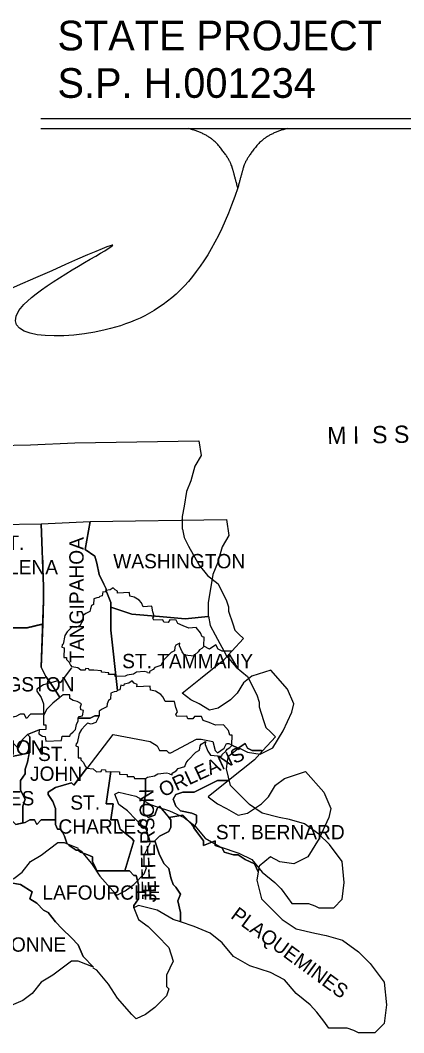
# Model space of a CAD drawing. Extents: x 0.19 to 2.82, y 0.04 to 1.79.
# Drawn here: x 2.4634 to 2.6012, y 1.3699 to 1.734 of the extents above; entities that cross this region are included whole.
import ezdxf

# ---------------------------------------------------------------- set-up
doc = ezdxf.new("R2010")
doc.units = 0
for name, color, linetype in [('Annotation', 7, 'Continuous'), ('Dist02', 7, 'Continuous'), ('Dist62', 7, 'Continuous'), ('Standard Info', 7, 'Continuous')]:
    doc.layers.add(name, color=color, linetype=linetype)

msp = doc.modelspace()

# ---------------------------------------------------------------- linework, layer by layer
at = {"layer": 'Annotation'}
for p, q in [((2.47085, 1.69871), (2.6123, 1.69871)), ((2.47085, 1.695), (2.6123, 1.695)), ((2.52387, 1.695), (2.55928, 1.695))]:
    msp.add_line(p, q, dxfattribs=at)
for points, degree in [([(2.54158, 1.67375), (2.54013, 1.67908), (2.53877, 1.68385), (2.53134, 1.69319), (2.52387, 1.695)], 2), ([(2.55928, 1.695), (2.55181, 1.69319), (2.54438, 1.68385), (2.54302, 1.67908), (2.54158, 1.67375)], 2), ([(2.54158, 1.67375), (2.53002, 1.63912), (2.4977, 1.61554), (2.42701, 1.62272), (2.54158, 1.67375), (2.42701, 1.62272)], 3)]:
    msp.add_open_spline(points, degree=degree, dxfattribs=at)
at = {"layer": 'Dist02'}
for points in [[(2.5294, 1.50908), (2.52924, 1.50867), (2.52865, 1.50808), (2.52782, 1.50758), (2.5274, 1.50692), (2.52615, 1.50575), (2.52607, 1.50533), (2.5224, 1.50567), (2.52157, 1.50683), (2.52065, 1.50908), (2.52074, 1.51), (2.51932, 1.50925), (2.51899, 1.50858), (2.51882, 1.50725), (2.51765, 1.50667), (2.51507, 1.504), (2.51449, 1.50308), (2.51399, 1.502), (2.51182, 1.50125), (2.51115, 1.5005), (2.5099, 1.49975), (2.50982, 1.49925), (2.50915, 1.49933), (2.50899, 1.49958), (2.50799, 1.49983), (2.50515, 1.49958), (2.50407, 1.49883), (2.50182, 1.4985), (2.50115, 1.49808)], [(2.53949, 1.50708), (2.53599, 1.50708), (2.53449, 1.50783), (2.53374, 1.50933), (2.5314, 1.50783), (2.5294, 1.50892)], [(2.52824, 1.49725), (2.53674, 1.50408)], [(2.53674, 1.50408), (2.53949, 1.50708)], [(2.4819, 1.50117), (2.47774, 1.49575), (2.47699, 1.4965), (2.47174, 1.495), (2.4694, 1.4935), (2.4694, 1.49275), (2.4709, 1.4905), (2.47174, 1.48817), (2.47174, 1.48442)], [(2.48982, 1.50033), (2.48824, 1.50025), (2.48807, 1.50075), (2.4869, 1.50092), (2.48674, 1.50033), (2.48515, 1.50025), (2.48407, 1.50117), (2.48199, 1.50142)], [(2.50115, 1.49808), (2.49757, 1.498), (2.4974, 1.49867), (2.49515, 1.49867), (2.49524, 1.49933), (2.49265, 1.4995), (2.49265, 1.50008), (2.48982, 1.50033)], [(2.5379, 1.4675), (2.53824, 1.46933), (2.54199, 1.47233), (2.54507, 1.47083), (2.54957, 1.47008), (2.55415, 1.47233), (2.5579, 1.47842), (2.56099, 1.48517), (2.56165, 1.48817), (2.5594, 1.4935), (2.5534, 1.50033), (2.54657, 1.49808), (2.54357, 1.49575), (2.54132, 1.492), (2.53899, 1.48967), (2.53449, 1.48667), (2.5314, 1.48592), (2.52765, 1.48817), (2.52465, 1.48967), (2.52165, 1.492), (2.52824, 1.49725)], [(2.47174, 1.48442), (2.46715, 1.48442), (2.46565, 1.48292), (2.4649, 1.48442), (2.4634, 1.48442), (2.46182, 1.48367), (2.45882, 1.48292), (2.45732, 1.48442), (2.45582, 1.48517), (2.45357, 1.48517), (2.44599, 1.48517), (2.44599, 1.48367), (2.44299, 1.48067), (2.44215, 1.47908), (2.44215, 1.47683), (2.44065, 1.47458), (2.4384, 1.47083), (2.4369, 1.4685)], [(2.51257, 1.45117), (2.51707, 1.44967), (2.52232, 1.44733), (2.52615, 1.44433), (2.5299, 1.43983), (2.53524, 1.43675), (2.54199, 1.4345), (2.54657, 1.43225), (2.55032, 1.42767), (2.5549, 1.42392), (2.55715, 1.42167), (2.5594, 1.41858), (2.56099, 1.41633), (2.56315, 1.41633), (2.56549, 1.41633), (2.56699, 1.41633), (2.56924, 1.41558), (2.57074, 1.41483), (2.57607, 1.41483), (2.57907, 1.41792), (2.57982, 1.42392), (2.57907, 1.4315), (2.57457, 1.43758), (2.57074, 1.44133), (2.56549, 1.44508), (2.56015, 1.44658), (2.5564, 1.44733), (2.55032, 1.44883), (2.54582, 1.45192), (2.53974, 1.45792), (2.53899, 1.45875), (2.53749, 1.46475), (2.5379, 1.46742)], [(2.4974, 1.45567), (2.4989, 1.45642), (2.50499, 1.45492), (2.51024, 1.45192), (2.51257, 1.45117)], [(2.48407, 1.43608), (2.48532, 1.43525), (2.48907, 1.43075), (2.49207, 1.42617), (2.49665, 1.42092), (2.49815, 1.41942), (2.50115, 1.42092), (2.50424, 1.42317), (2.50799, 1.427), (2.50874, 1.42917), (2.50799, 1.43), (2.50799, 1.43375), (2.51024, 1.43825), (2.50874, 1.44283), (2.50499, 1.44658), (2.50199, 1.44967), (2.4989, 1.45192), (2.4974, 1.45567)], [(2.41574, 1.43492), (2.41799, 1.43225), (2.42782, 1.4285), (2.43465, 1.42617), (2.44449, 1.42167), (2.44749, 1.42167), (2.45432, 1.42242), (2.45582, 1.42317), (2.46115, 1.42542), (2.46415, 1.42767), (2.46715, 1.4315), (2.4709, 1.43375), (2.47699, 1.43825), (2.47924, 1.43825), (2.48424, 1.43633)]]:
    msp.add_lwpolyline(points, dxfattribs=at)
at = {"layer": 'Dist62'}
for p, q in [((2.44915, 1.581), (2.46715, 1.58125)), ((2.46715, 1.58125), (2.48307, 1.582)), ((2.48307, 1.582), (2.52757, 1.58275))]:
    msp.add_line(p, q, dxfattribs=at)
for points in [[(2.52757, 1.58275), (2.5284, 1.57742), (2.52615, 1.57367), (2.52465, 1.56833), (2.52315, 1.56458), (2.52232, 1.55925), (2.52165, 1.5555), (2.52165, 1.551)], [(2.52174, 1.551), (2.52232, 1.548), (2.5239, 1.54492), (2.52765, 1.53808), (2.53074, 1.53433), (2.53449, 1.53133), (2.53749, 1.52525), (2.53824, 1.523), (2.53824, 1.5215), (2.53974, 1.51692), (2.54049, 1.51467), (2.54199, 1.51317), (2.54357, 1.51167), (2.53949, 1.50708)], [(2.5294, 1.50908), (2.52949, 1.51217), (2.52874, 1.51225), (2.52824, 1.51367), (2.52665, 1.51558), (2.52399, 1.51542), (2.5219, 1.51625), (2.51999, 1.517), (2.5194, 1.51825), (2.51715, 1.51833), (2.51657, 1.51742), (2.51499, 1.5175), (2.51465, 1.51833), (2.5114, 1.51825), (2.51107, 1.51892), (2.51157, 1.51975), (2.51107, 1.52125), (2.51065, 1.52325), (2.50757, 1.52308), (2.50699, 1.5245), (2.50615, 1.5255), (2.5044, 1.52658), (2.50282, 1.52683), (2.50265, 1.52817), (2.49832, 1.528), (2.4984, 1.52867), (2.49749, 1.52917), (2.49682, 1.52983), (2.49574, 1.52917), (2.49415, 1.52892), (2.49399, 1.52833), (2.49307, 1.52842), (2.49282, 1.527), (2.49207, 1.52675)], [(2.49207, 1.52675), (2.49165, 1.52642), (2.4909, 1.52625), (2.48982, 1.52592), (2.48974, 1.52392), (2.48907, 1.52358), (2.48865, 1.52233), (2.48849, 1.52142), (2.48699, 1.52067), (2.48607, 1.51992), (2.48607, 1.51842)], [(2.48607, 1.51842), (2.48549, 1.51742), (2.48499, 1.51633), (2.4834, 1.51567), (2.48224, 1.516), (2.48149, 1.51525), (2.48024, 1.51408), (2.47949, 1.51275), (2.4789, 1.50958), (2.47849, 1.50942), (2.4784, 1.50858), (2.47924, 1.50833), (2.47915, 1.50483), (2.48007, 1.50483), (2.48007, 1.50417), (2.4809, 1.50325), (2.48149, 1.50208), (2.48199, 1.50142)], [(2.53949, 1.50708), (2.53599, 1.50708), (2.53449, 1.50783), (2.53374, 1.50933), (2.5314, 1.50783), (2.5294, 1.50892)], [(2.4819, 1.50117), (2.47774, 1.49575), (2.47699, 1.4965), (2.47174, 1.495), (2.4694, 1.4935), (2.4694, 1.49275), (2.4709, 1.4905), (2.47174, 1.48817), (2.47174, 1.48442)], [(2.47174, 1.48442), (2.46715, 1.48442), (2.46565, 1.48292), (2.4649, 1.48442), (2.4634, 1.48442), (2.46182, 1.48367), (2.46115, 1.4835)]]:
    msp.add_lwpolyline(points, dxfattribs=at)
at = {"layer": 'Standard Info'}
for p, q in [((2.45121, 1.55259), (2.47101, 1.55286)), ((2.47101, 1.55286), (2.48852, 1.55369)), ((2.48852, 1.55369), (2.53747, 1.55451)), ((2.53096, 1.51959), (2.53105, 1.51968)), ((2.47156, 1.51684), (2.4712, 1.51684)), ((2.47019, 1.4788), (2.46606, 1.47715)), ((2.46606, 1.47715), (2.47019, 1.4788)), ((2.46606, 1.47715), (2.47019, 1.4788)), ((2.46441, 1.44552), (2.46441, 1.44534)), ((2.51685, 1.44726), (2.51675, 1.44726)), ((2.52583, 1.4436), (2.52592, 1.44387))]:
    msp.add_line(p, q, dxfattribs=at)
for points in [[(2.47101, 1.55286), (2.47184, 1.53041), (2.47184, 1.52546), (2.47156, 1.51684)], [(2.4777, 1.49044), (2.4777, 1.49044), (2.47605, 1.49301), (2.4744, 1.49548), (2.47266, 1.49796), (2.47101, 1.50135), (2.47184, 1.52546), (2.47184, 1.53041), (2.47101, 1.55286)], [(2.48852, 1.55369), (2.48678, 1.5437), (2.49017, 1.54122), (2.491, 1.53875), (2.49182, 1.53462), (2.49347, 1.53123), (2.4943, 1.52958), (2.4943, 1.52876), (2.49595, 1.52463), (2.49595, 1.51464), (2.49842, 1.49301)], [(2.49595, 1.52298), (2.49595, 1.52463), (2.4943, 1.52876), (2.4943, 1.52958), (2.49347, 1.53123), (2.49182, 1.53462), (2.491, 1.53875), (2.49017, 1.54122), (2.48678, 1.5437), (2.48852, 1.55369)], [(2.53747, 1.55451), (2.53839, 1.54874), (2.53591, 1.54461), (2.53426, 1.53875), (2.53261, 1.53462), (2.5317, 1.52876), (2.53096, 1.52463), (2.53096, 1.51959)], [(2.53096, 1.51959), (2.52262, 1.51876), (2.51345, 1.51959), (2.50346, 1.52041), (2.49595, 1.52298)], [(2.49842, 1.49301), (2.49595, 1.51464), (2.49595, 1.52298)], [(2.49595, 1.52298), (2.50346, 1.52041), (2.51345, 1.51959), (2.52262, 1.51876), (2.53096, 1.51959)], [(2.53105, 1.51968), (2.5317, 1.51629), (2.53344, 1.51299), (2.53756, 1.50547), (2.54095, 1.50135), (2.54508, 1.49796), (2.54838, 1.49136), (2.5492, 1.48879), (2.5492, 1.48714), (2.55085, 1.48219), (2.55168, 1.47971), (2.55333, 1.47806), (2.55507, 1.47632), (2.55058, 1.47137)], [(2.46606, 1.47715), (2.46441, 1.4755), (2.46267, 1.4722), (2.46185, 1.47302), (2.4602, 1.47467), (2.45855, 1.47715), (2.45442, 1.48136), (2.45103, 1.48384), (2.4469, 1.48714), (2.44443, 1.48971), (2.44113, 1.49218), (2.43939, 1.49548), (2.43856, 1.49878), (2.43856, 1.50208), (2.43856, 1.5063), (2.43939, 1.50877), (2.44113, 1.51207), (2.44351, 1.51464), (2.44415, 1.51556)], [(2.4712, 1.51684), (2.4657, 1.51546), (2.44397, 1.51546)], [(2.44434, 1.51546), (2.46606, 1.51546), (2.47156, 1.51684)], [(2.44434, 1.51546), (2.46606, 1.51546), (2.47156, 1.51684)], [(2.47156, 1.51684), (2.47101, 1.50135), (2.47266, 1.49796), (2.4744, 1.49548), (2.47605, 1.49301), (2.4777, 1.49044)], [(2.53949, 1.47348), (2.53958, 1.47687), (2.53875, 1.47696), (2.5382, 1.47861), (2.53646, 1.48063), (2.53353, 1.48045), (2.53124, 1.48146), (2.52913, 1.48219), (2.52849, 1.48356), (2.52601, 1.48366), (2.52537, 1.48274), (2.52363, 1.48274), (2.52326, 1.48375), (2.51969, 1.48356), (2.51932, 1.4843), (2.51987, 1.48531), (2.51932, 1.48686), (2.51886, 1.48906), (2.51547, 1.48897), (2.51483, 1.49053), (2.51391, 1.49154), (2.51199, 1.49273), (2.51025, 1.4931), (2.51006, 1.49456), (2.5053, 1.49429), (2.50539, 1.49511), (2.50438, 1.49566), (2.50365, 1.4964), (2.50245, 1.49566), (2.50071, 1.4953), (2.50053, 1.49466), (2.49952, 1.49484), (2.49925, 1.49319), (2.49842, 1.49301)], [(2.49842, 1.49301), (2.49796, 1.49255), (2.49714, 1.49246), (2.49595, 1.492), (2.49585, 1.48989), (2.49512, 1.48943), (2.49466, 1.48815), (2.49448, 1.48705), (2.49283, 1.48631), (2.49182, 1.48549), (2.49182, 1.48384)], [(2.4777, 1.49044), (2.47514, 1.48842), (2.47303, 1.48622), (2.47175, 1.48402), (2.47184, 1.48063), (2.47266, 1.48063), (2.47266, 1.47889), (2.47019, 1.4788), (2.46606, 1.47715)], [(2.4843, 1.48301), (2.48458, 1.48356), (2.48577, 1.48384), (2.48614, 1.48576), (2.48522, 1.48604), (2.48504, 1.48714), (2.4854, 1.48815), (2.48394, 1.48906), (2.48247, 1.48934), (2.48128, 1.49007), (2.48128, 1.49136), (2.4789, 1.49136), (2.4777, 1.49044)], [(2.44681, 1.48714), (2.45103, 1.48384), (2.45442, 1.48136), (2.45855, 1.47715), (2.4602, 1.47467), (2.46185, 1.47302), (2.46267, 1.4722), (2.46441, 1.4755), (2.46606, 1.47715), (2.46689, 1.47632), (2.46689, 1.47055)], [(2.47019, 1.4788), (2.4701, 1.47733), (2.47147, 1.4766), (2.47239, 1.47641), (2.47266, 1.47476), (2.47825, 1.47495), (2.47853, 1.47651), (2.48128, 1.47651), (2.48146, 1.47724), (2.48247, 1.47806), (2.4833, 1.47898), (2.48366, 1.48072), (2.4843, 1.4821), (2.4843, 1.48301)], [(2.49182, 1.48384), (2.49118, 1.48265), (2.49063, 1.48146), (2.48889, 1.48081), (2.4876, 1.48118), (2.48678, 1.48036), (2.4854, 1.47898), (2.48458, 1.47751), (2.48394, 1.47403), (2.48348, 1.47394), (2.48339, 1.47302), (2.4843, 1.47275), (2.48421, 1.46881), (2.48522, 1.46881), (2.48522, 1.46807), (2.48614, 1.46706), (2.48678, 1.46578), (2.48733, 1.46505)], [(2.49182, 1.48384), (2.49017, 1.48384), (2.48852, 1.48301), (2.4843, 1.48301)], [(2.4843, 1.48301), (2.48852, 1.48301), (2.49017, 1.48384), (2.49182, 1.48384)], [(2.46441, 1.44552), (2.46441, 1.44891), (2.46441, 1.45139), (2.46515, 1.45386), (2.4635, 1.45716), (2.4635, 1.45891), (2.4635, 1.46056), (2.46515, 1.46303), (2.46515, 1.46468), (2.46606, 1.46716), (2.46689, 1.47137), (2.46689, 1.47632), (2.46606, 1.47715)], [(2.48742, 1.46496), (2.49677, 1.47715), (2.51006, 1.47467), (2.51263, 1.47302), (2.51345, 1.47137), (2.51593, 1.47137), (2.51675, 1.47055), (2.51758, 1.47055), (2.52675, 1.4755), (2.5284, 1.4755), (2.53261, 1.47467), (2.53344, 1.47137), (2.53426, 1.47055), (2.53674, 1.4722), (2.53756, 1.47385), (2.53839, 1.47385), (2.5394, 1.47339)], [(2.48742, 1.46496), (2.49677, 1.47715), (2.51006, 1.47467), (2.51263, 1.47302), (2.51345, 1.47137), (2.51593, 1.47137), (2.51675, 1.47055), (2.51758, 1.47055), (2.52675, 1.4755), (2.5284, 1.4755), (2.53261, 1.47467), (2.53344, 1.47137), (2.53426, 1.47055), (2.53674, 1.4722), (2.53756, 1.47385), (2.53839, 1.47385), (2.5394, 1.47339)], [(2.50841, 1.46138), (2.50915, 1.46184), (2.51162, 1.4623), (2.51281, 1.46303), (2.51593, 1.4634), (2.51703, 1.46312), (2.51721, 1.46285), (2.51795, 1.46266), (2.51804, 1.46321), (2.51941, 1.46413), (2.52015, 1.46496), (2.52253, 1.46569), (2.52308, 1.46697), (2.52372, 1.46789), (2.52656, 1.47082), (2.52785, 1.47146), (2.52803, 1.47302), (2.5284, 1.47366), (2.52995, 1.47458), (2.52986, 1.47357), (2.53087, 1.4711), (2.53179, 1.46972), (2.53582, 1.46936), (2.53591, 1.46991), (2.53729, 1.4711), (2.53775, 1.47192), (2.53866, 1.47247), (2.5393, 1.47311), (2.53949, 1.47348)], [(2.53949, 1.4733), (2.54169, 1.4722), (2.54425, 1.47385), (2.54508, 1.4722), (2.54673, 1.47137), (2.55058, 1.47137)], [(2.55003, 1.47137), (2.54673, 1.47137), (2.54508, 1.4722), (2.54425, 1.47385), (2.54169, 1.4722), (2.53949, 1.4733)], [(2.55058, 1.47137), (2.54755, 1.46807)], [(2.46689, 1.47055), (2.4469, 1.46642), (2.44351, 1.46642), (2.44351, 1.46386), (2.44278, 1.46386), (2.44021, 1.46138), (2.43691, 1.46056), (2.43526, 1.46138), (2.43444, 1.46138), (2.43279, 1.46138), (2.43114, 1.46138), (2.43022, 1.46221), (2.42857, 1.46056)], [(2.44021, 1.46147), (2.44278, 1.46386), (2.44351, 1.46386), (2.44351, 1.46642), (2.4469, 1.46642), (2.46689, 1.47055)], [(2.4667, 1.47055), (2.46606, 1.46716), (2.46515, 1.46468), (2.46515, 1.46303), (2.4635, 1.46056), (2.4635, 1.45891), (2.4635, 1.45716), (2.46515, 1.45386), (2.46441, 1.45139), (2.46441, 1.44891), (2.46441, 1.44552)], [(2.54755, 1.46807), (2.5382, 1.46056)], [(2.48724, 1.46486), (2.48265, 1.45891), (2.48183, 1.45973), (2.47605, 1.45808), (2.47349, 1.45643), (2.47349, 1.45551), (2.47514, 1.45304), (2.47605, 1.45056), (2.47605, 1.44644)], [(2.47605, 1.44644), (2.47605, 1.45056), (2.47514, 1.45304), (2.47349, 1.45551), (2.47349, 1.45643), (2.47605, 1.45808), (2.48183, 1.45973), (2.48265, 1.45891), (2.48724, 1.46486)], [(2.48733, 1.46505), (2.48962, 1.46477), (2.49081, 1.46376), (2.49255, 1.46386), (2.49274, 1.4645), (2.49402, 1.46441), (2.4942, 1.46376), (2.49595, 1.46386)], [(2.49595, 1.46386), (2.4943, 1.45221), (2.49677, 1.45221), (2.49595, 1.44644), (2.49842, 1.44644), (2.49934, 1.44305), (2.50346, 1.43975), (2.50429, 1.43892), (2.50099, 1.42811)], [(2.50099, 1.42811), (2.50429, 1.43892), (2.50346, 1.43975), (2.49934, 1.44305), (2.49842, 1.44644), (2.49595, 1.44644), (2.49677, 1.45221), (2.4943, 1.45221), (2.49595, 1.46386)], [(2.49595, 1.46386), (2.49906, 1.46367), (2.49906, 1.46294), (2.5019, 1.46276), (2.50181, 1.46202), (2.50429, 1.46202), (2.50447, 1.46138), (2.50841, 1.46138)], [(2.5382, 1.46056), (2.53096, 1.45469), (2.53426, 1.45221), (2.53756, 1.45056), (2.54169, 1.44809), (2.54508, 1.44891), (2.55003, 1.45221), (2.5526, 1.45469), (2.55507, 1.45891), (2.55837, 1.46138), (2.56589, 1.46386), (2.57249, 1.45643), (2.57496, 1.45056), (2.57423, 1.44726), (2.57084, 1.43975), (2.56671, 1.43315), (2.56167, 1.43058), (2.55672, 1.43141), (2.55333, 1.43315), (2.5492, 1.42976), (2.54884, 1.42774)], [(2.50841, 1.46138), (2.50841, 1.45551), (2.50768, 1.45139), (2.50768, 1.44891), (2.50933, 1.44726), (2.5118, 1.44809), (2.51263, 1.45056), (2.51345, 1.45139), (2.51758, 1.44644), (2.51758, 1.44387), (2.51675, 1.44222), (2.5151, 1.4414), (2.51345, 1.44057), (2.5118, 1.43892), (2.51263, 1.43645), (2.51345, 1.43388), (2.5151, 1.43058), (2.51675, 1.42893), (2.51758, 1.42563), (2.5184, 1.42316), (2.51932, 1.42224), (2.52097, 1.41976), (2.52005, 1.41729), (2.52097, 1.41316), (2.52097, 1.40977)], [(2.51694, 1.44726), (2.51345, 1.45139), (2.51263, 1.45056), (2.5118, 1.44809), (2.50933, 1.44726), (2.50768, 1.44891), (2.50768, 1.45139), (2.50841, 1.45551), (2.50841, 1.46138)], [(2.5382, 1.46056), (2.53591, 1.46056), (2.53426, 1.46056), (2.53261, 1.45973), (2.52922, 1.45808), (2.52592, 1.45643), (2.5218, 1.45643), (2.51932, 1.45551), (2.5184, 1.45386), (2.51932, 1.45139), (2.52097, 1.44974), (2.5251, 1.44891), (2.52675, 1.44809), (2.52675, 1.44552), (2.52592, 1.44387)], [(2.52592, 1.44387), (2.52675, 1.44552), (2.52675, 1.44809), (2.5251, 1.44891), (2.52097, 1.44974), (2.51932, 1.45139), (2.5184, 1.45386), (2.51932, 1.45551), (2.5218, 1.45643), (2.52592, 1.45643), (2.52922, 1.45808), (2.53261, 1.45973), (2.53426, 1.46056), (2.53591, 1.46056), (2.5382, 1.46056)], [(2.43774, 1.42893), (2.43939, 1.43141), (2.44186, 1.43553), (2.44351, 1.4381), (2.44351, 1.44057), (2.44443, 1.44222), (2.44773, 1.44552), (2.44773, 1.44726), (2.45607, 1.44726), (2.45855, 1.44726), (2.4602, 1.44644), (2.46185, 1.44479), (2.46515, 1.44552), (2.46689, 1.44644), (2.46854, 1.44644), (2.46936, 1.44479), (2.47101, 1.44644), (2.47605, 1.44644)], [(2.46441, 1.44534), (2.46185, 1.44479), (2.4602, 1.44644), (2.45855, 1.44726), (2.45607, 1.44726), (2.44773, 1.44726), (2.44773, 1.44552), (2.4469, 1.4447)], [(2.47605, 1.44644), (2.47101, 1.44644), (2.46936, 1.44479), (2.46854, 1.44644), (2.46689, 1.44644), (2.46515, 1.44552), (2.46441, 1.44534)], [(2.47605, 1.44644), (2.47605, 1.44479), (2.47679, 1.44305), (2.4777, 1.44305), (2.47853, 1.44222), (2.47935, 1.44057), (2.48018, 1.4381), (2.481, 1.43727), (2.48348, 1.43553), (2.4843, 1.43553), (2.48513, 1.4348), (2.4877, 1.43388), (2.48935, 1.43315), (2.48935, 1.43141), (2.49017, 1.42976), (2.491, 1.42811), (2.50264, 1.42811), (2.50429, 1.42646), (2.50511, 1.42646), (2.50594, 1.42316), (2.50594, 1.42059), (2.50594, 1.41811), (2.50429, 1.41564), (2.50429, 1.41481)], [(2.50099, 1.42811), (2.491, 1.42811), (2.49017, 1.42976), (2.48935, 1.43141), (2.48935, 1.43315), (2.4877, 1.43388), (2.48513, 1.4348), (2.4843, 1.43553), (2.48348, 1.43553), (2.481, 1.43727), (2.48018, 1.4381), (2.47935, 1.44057), (2.47853, 1.44222), (2.4777, 1.44305), (2.47679, 1.44305), (2.47605, 1.44479), (2.47605, 1.44644)], [(2.52097, 1.40977), (2.52097, 1.41316), (2.52005, 1.41729), (2.52097, 1.41976), (2.51932, 1.42224), (2.5184, 1.42316), (2.51758, 1.42563), (2.51675, 1.42893), (2.5151, 1.43058), (2.51345, 1.43388), (2.51263, 1.43645), (2.5118, 1.43892), (2.51345, 1.44057), (2.5151, 1.4414), (2.51675, 1.44222), (2.51758, 1.44387), (2.51758, 1.44644), (2.51685, 1.44726)], [(2.52574, 1.44378), (2.5251, 1.44479), (2.5218, 1.44809), (2.51675, 1.44726)], [(2.51675, 1.44726), (2.5218, 1.44809), (2.5251, 1.44479), (2.52574, 1.44378)], [(2.54884, 1.42774), (2.54755, 1.43058), (2.54425, 1.43223), (2.54169, 1.43388), (2.54004, 1.43388), (2.53674, 1.4348), (2.53591, 1.43645), (2.53344, 1.43727), (2.53344, 1.43892), (2.52922, 1.43727), (2.52922, 1.43892), (2.52675, 1.44222), (2.52583, 1.4436)], [(2.52583, 1.4436), (2.52675, 1.44222), (2.52922, 1.43892), (2.52922, 1.43727), (2.53344, 1.43892), (2.53344, 1.43727), (2.53591, 1.43645), (2.53674, 1.4348), (2.54004, 1.43388), (2.54169, 1.43388), (2.54425, 1.43223), (2.54755, 1.43058), (2.54884, 1.42774)], [(2.43774, 1.42893), (2.44773, 1.42893), (2.44773, 1.43141), (2.45103, 1.43223), (2.45277, 1.43388), (2.45525, 1.43223), (2.45607, 1.43058), (2.45772, 1.42728), (2.45937, 1.42389), (2.4635, 1.42316), (2.46771, 1.42059), (2.46689, 1.41811), (2.46936, 1.41646), (2.47184, 1.41399), (2.47349, 1.41316), (2.47605, 1.40977), (2.47853, 1.4073), (2.48183, 1.404), (2.4843, 1.40152), (2.48605, 1.39731), (2.4898, 1.39346)], [(2.4898, 1.39346), (2.48605, 1.39731), (2.4843, 1.40152), (2.48183, 1.404), (2.47853, 1.4073), (2.47605, 1.40977), (2.47349, 1.41316), (2.47184, 1.41399), (2.46936, 1.41646), (2.46689, 1.41811), (2.46771, 1.42059), (2.4635, 1.42316), (2.45937, 1.42389), (2.45772, 1.42728), (2.45607, 1.43058), (2.45525, 1.43223), (2.45277, 1.43388), (2.45103, 1.43223), (2.44773, 1.43141), (2.44773, 1.42893), (2.43774, 1.42893)], [(2.50429, 1.41481), (2.50429, 1.41564), (2.50594, 1.41811), (2.50594, 1.42059), (2.50594, 1.42316), (2.50511, 1.42646), (2.50429, 1.42646), (2.50264, 1.42811), (2.50099, 1.42811)], [(2.54884, 1.42774), (2.54838, 1.42481), (2.55003, 1.41811), (2.55085, 1.41729), (2.55755, 1.4106), (2.5625, 1.4073), (2.56919, 1.40565), (2.57331, 1.40482), (2.57918, 1.40317), (2.58495, 1.39896), (2.58917, 1.39483), (2.59412, 1.38814), (2.59495, 1.37989), (2.59412, 1.3732), (2.59082, 1.3699), (2.58495, 1.3699), (2.5833, 1.37072), (2.58083, 1.37155), (2.57918, 1.37155), (2.57661, 1.37155), (2.57423, 1.37155), (2.57249, 1.37402), (2.57001, 1.37732), (2.56754, 1.37989), (2.5625, 1.38401), (2.55837, 1.38896), (2.55333, 1.39153), (2.5459, 1.39401), (2.54004, 1.39731), (2.53591, 1.40226), (2.5317, 1.40565), (2.52592, 1.40812), (2.52097, 1.40977)], [(2.50429, 1.41481), (2.50594, 1.4106), (2.50933, 1.40812), (2.51263, 1.40482), (2.51675, 1.40061), (2.5184, 1.39566), (2.51593, 1.39061), (2.51593, 1.38649), (2.51675, 1.38566), (2.51593, 1.38319), (2.5118, 1.37897), (2.50841, 1.3765), (2.50511, 1.37485), (2.50346, 1.3765), (2.49842, 1.38236), (2.49512, 1.38731), (2.491, 1.39236), (2.48962, 1.39318)], [(2.52097, 1.40977), (2.5184, 1.4106), (2.51263, 1.41399), (2.50594, 1.41564), (2.50429, 1.41481)], [(2.4898, 1.39346), (2.4843, 1.39566), (2.48183, 1.39566), (2.47514, 1.39061), (2.47101, 1.38814), (2.46771, 1.38401), (2.46441, 1.38154), (2.45855, 1.37897), (2.4569, 1.37824), (2.44938, 1.37732), (2.44608, 1.37732), (2.43526, 1.38236), (2.42775, 1.38484), (2.41693, 1.38896), (2.41445, 1.39199)]]:
    msp.add_lwpolyline(points, dxfattribs=at)

# ---------------------------------------------------------------- texts
for s, height, p in [('STATE PROJECT', 0.01067, (2.47681, 1.72315)), ('S.P. H.001234', 0.01067, (2.47681, 1.70608)), ('ST.', 0.005147, (2.45422, 1.54354)), ('WASHINGTON', 0.005147, (2.49683, 1.53691)), ('HELENA', 0.005146, (2.44946, 1.53474)), ('ST. TAMMANY', 0.0051469, (2.50004, 1.50098)), ('LIVINGSTON', 0.005147, (2.44124, 1.49262)), ('ASCENSION', 0.005147, (2.43165, 1.46991)), ('ST.', 0.005147, (2.46982, 1.46761)), ('JOHN', 0.005146, (2.46694, 1.46048)), ('JAMES', 0.005147, (2.44556, 1.45166)), ('ST.', 0.005147, (2.48141, 1.45011)), ('CHARLES', 0.005147, (2.47716, 1.44149)), ('ST. BERNARD', 0.0051469, (2.5337, 1.43947)), ('LAFOURCHE', 0.005146, (2.47142, 1.41775)), ('TERREBONNE', 0.005147, (2.43216, 1.39905))]:
    msp.add_text(s, height=height, dxfattribs=at).set_placement(p)
for s, height, rotation, p in [('M I  S S I  S S I  P P I', 0.0062, 1.0059, (2.57375, 1.58155)), ('TANGIPAHOA', 0.005147, 90.2537, (2.48637, 1.50301)), ('ORLEANS', 0.005146, 24.9246, (2.51469, 1.45451)), ('JEFFERSON', 0.005147, 91.4837, (2.51233, 1.41679)), ('PLAQUEMINES', 0.0051469, 323.7253, (2.53869, 1.41133))]:
    msp.add_text(s, height=height, rotation=rotation, dxfattribs=at).set_placement(p)

doc.saveas('drawing.dxf')
